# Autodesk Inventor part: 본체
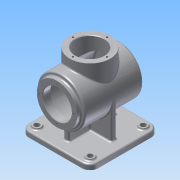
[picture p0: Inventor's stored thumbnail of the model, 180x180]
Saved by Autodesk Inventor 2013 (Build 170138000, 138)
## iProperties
Created: 2015-07
Part Number: 본체
Material: 알루미늄 6061
Document SubType Name: Modeling
Designer: Administrator
Density: 2.71 g/cm^3
Mass: 1397.25 g
Surface Area: 1275.9 cm^2
Volume: 515.592 cm^3
Author: Administrator
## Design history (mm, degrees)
sketch "스케치2"
  geometry: L1 (50, -65)-(-50, -65); L2 (-65, -50)-(-65, 50); L3 (-50, 65)-(50, 65); L4 (65, 50)-(65, -50); L5 (65, -65)-(-65, 65); L6 (-65, -65)-(65, 65); A1 r 15 centre (50, -50) between (50, -65) and (65, -50); A2 r 15 centre (-50, -50) between (-65, -50) and (-50, -65); A3 r 15 centre (-50, 50) between (-50, 65) and (-65, 50); A4 r 15 centre (50, 50) between (65, 50) and (50, 65); 3 further points
  constraints: 12 end point, 8 point on circle, 8 point on line, 8 tangent, 4 centre point, 3 equal radius, 3 midpoint, 2 parallel, 1 coincident, 1 horizontal, 1 perpendicular
  dimensions: "d0" = 130 distance of L5.end L6.end; "d2" = 130 distance of L6.start L5.end; "d3" = 15 radius of A1
extrude "돌출1" new body sketch "스케치2" distance "d4" = 10; taper "d5" = 0 deg
sketch "스케치3"
  geometry: L1 (50, 0)-(-50, 0) reference; L2 (50, 10)-(-50, 10) reference; L3 (-65, 0)-(-65, 10) reference; C1 r 45 at (0, 78); 1 further point
  constraints: 1 centre point
  dimensions: "d6" = 90 diameter of C1; "d8" = 78 distance from line of L1 C1.centre
extrude "돌출2" join sketch "스케치3" stored distance "d9" = 110; taper "d10" = 0 deg
sketch "스케치4"
  geometry: C1 r 45 at (0, 0) reference; C2 r 38 at (0, 0); 1 further point
  constraints: 1 centre point, 1 coincident
  dimensions: "d11" = 76 diameter of C2
extrude "돌출3" join sketch "스케치4" distance "d12" = 7; taper "d13" = 0 deg
sketch "스케치5"
  geometry: L1 (50, 10)-(-50, 10) reference; L2 (-45, 78)-(-45, 10); L3 (45, 78)-(45, 10); A1 r 45 centre (0, 78) between (-45, 78) and (45, 78) reference; 1 further point
  constraints: 4 end point, 2 perpendicular, 2 point on circle, 2 point on line, 2 tangent
extrude "돌출4" join sketch "스케치5" stored distance "d15" = 10; taper "d16" = 0 deg
sketch "스케치6"
  geometry: L1 (33, -55)-(33, 55) reference; L2 (10, -50)-(10, 50) reference; L3 (33, 45)-(10, 45); 1 further point
  constraints: 2 end point, 2 point on line, 1 perpendicular
  dimensions: "d17" = 45 distance from line of point (0, 0) L3
feature "리브1" sketch "스케치6" dims "d18" = 1, "d19" = 10, "d20" = 0, "d21" = 0, "d22" = 1, "d23" = 1
sketch "스케치7"
  geometry: C1 r 7.5 at (50, -50); A1 r 15 centre (50, -50) between (50, -65) and (65, -50) reference; 1 further point
  constraints: 1 centre point, 1 coincident
  dimensions: "d24" = 15 diameter of C1
extrude "돌출5" join sketch "스케치7" distance "d25" = 3; taper "d26" = 0 deg
hole "구멍1" diameter "d29" = 10; stored, may be unused: countersink angle "d33" = 90 deg, drill point angle "d35" = 118 deg; dims "d27" = 10, "d28" = 10, "d30" = 6, "d31" = 4, "d32" = 2, "d34" = 8
sketch "스케치8"
  geometry: L1 (40, 62)-(116, 62) reference; L2 (116, 62)-(116, 55) reference; L3 (116, 55)-(123, 55) reference; L4 (123, 55)-(123, -55) reference; L5 (123, -55)-(33, -55) reference; L6 (33, -55)-(33, -45) reference; L7 (33, -45)-(10, -45) reference; L8 (10, -45)-(10, -65) reference; L9 (10, -65)-(0, -65) reference; L10 (0, -65)-(0, 65) reference; L11 (0, 65)-(10, 65) reference; L12 (10, 65)-(10, 45) reference; L13 (10, 45)-(33, 45) reference; L14 (33, 45)-(33, 55) reference; L15 (33, 55)-(40, 55) reference; L16 (40, 55)-(40, 62) reference; L17 (78, -55)-(78, 62); L18 (105, 62)-(105, 48); L19 (105, 48)-(118, 48); L20 (118, -48)-(78, -48); L21 (105, 62)-(78, 62); L22 (118, 48)-(118, -48); 1 further point
  constraints: 12 end point, 3 perpendicular, 2 midpoint, 2 point on line, 1 collinear, 1 parallel
  dimensions: "d44" = 54 diameter of L18 L17; "d45" = 14 distance of L18.start L18.end; "d46" = 80 diameter of L22 L17; "d47" = 96 distance of L19.end L20.start
revolve "회전1" sketch "스케치8" stored, may be unused: angle "d48" = 90 deg
sketch "스케치9"
  geometry: C1 r 27 at (0, 0) reference; C2 r 38 at (0, 0) reference; 2 further points
  dimensions: "d49" = 32 distance of C1.centre point (0, 32)
hole "구멍2" sketch "스케치9" at (0, 32) diameter "d50" = 3.242; stored, may be unused: countersink angle "d54" = 90 deg, drill point angle "d56" = 118 deg; dims "d51" = 8, "d52" = 4, "d53" = 2, "d55" = 10
node "작업 평면1"
sketch "스케치10"
  geometry: C1 r 38 at (0, 0); 1 further point
  constraints: 1 centre point, 1 coincident
  dimensions: "d61" = 76 diameter of C1
extrude "돌출6" join sketch "스케치10" stored distance "d62" = 3; taper "d63" = 0 deg
hole "구멍3" diameter "d66" = 54; stored, may be unused: countersink angle "d70" = 90 deg, drill point angle "d72" = 0 deg; dims "d64" = 10, "d65" = 10, "d67" = 8, "d68" = 4, "d69" = 2, "d71" = 10
sketch "스케치11"
  geometry: 2 further points
  dimensions: "d73" = 32 distance of point (0, 0) point (0, 32)
hole "구멍4" sketch "스케치11" at (0, 32) diameter "d74" = 3.242; stored, may be unused: countersink angle "d78" = 90 deg, drill point angle "d80" = 118 deg; dims "d75" = 8, "d76" = 4, "d77" = 2, "d79" = 10
fillet "모깎기1" dims "d84" = 3
fillet "모깎기2" dims "d85" = 3
fillet "모깎기3" dims "d86" = 3
chamfer "모따기1" distance "d87" = 1; stored, may be unused: second distance "d88" = 2, angle "d89" = 45 deg
sketch "스케치12"
  geometry: C1 r 42 at (0, 0) reference; 2 further points
  constraints: 1 coincident, 1 other
feature "엠보싱1" sketch "스케치12" dims "d0" = 130, "d2" = 130, "d3" = 15, "d90" = 0.5, "d91" = 0
node "솔리드1"
mirror "대칭1"
pattern_linear "직사각형 패턴1"
pattern_circular "원형 패턴1" dims angle "d58" = 360 deg
pattern_circular "원형 패턴2" dims angle "d82" = 360 deg
node "투영된 루프1"
node "투영된 루프2"
node "절단 모서리 투영1"
